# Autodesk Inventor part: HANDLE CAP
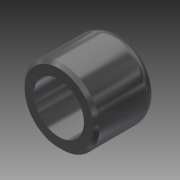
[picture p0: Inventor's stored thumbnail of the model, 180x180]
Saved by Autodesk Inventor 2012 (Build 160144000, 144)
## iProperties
Shininess: 64.0
Length Units: 11272
Angle Units: 11279
Time Units: 11290
Mass Units: 11286
Length Display Precision: 3
Angle Display Precision: 2
Compacted: True
Part Number: HANDLE CAP
Document SubType Name: Modeling
Created: 2003-11
Designer: Autodesk, Inc.
Manufacturer: Standard
Standards Organization: Custom
Mass: 2.20956 g
Surface Area: 17.857 cm^2
Volume: 2.37587 cm^3
Density: 0.93 g/cm^3
Material: Rubber
Density: 0.0
Volumn: 0.0
Area: 0.0
PropertySet Name: Model Information
Control State: 0
Master: False
Checked Out: False
Author: Autodesk, Inc.
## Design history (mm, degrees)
sketch "Sketch1"
  geometry: C1 r 9.525 at (0, 0); C2 r 6.35 at (0, 0); 1 further point
  constraints: 2 centre point, 2 coincident
  dimensions: "d0" = 19.05 diameter of C1; "d1" = 12.7 diameter of C2
extrude "Extrusion1" new body sketch "Sketch1" distance "d2" = 15.875; taper "d3" = 0 deg
chamfer "Chamfer1" distance "d5" = 0.7874; stored, may be unused: second distance "d6" = 3.175, angle "d7" = 45 deg
fillet "Fillet2" dims "d8" = 3.175
body "Solid1"
